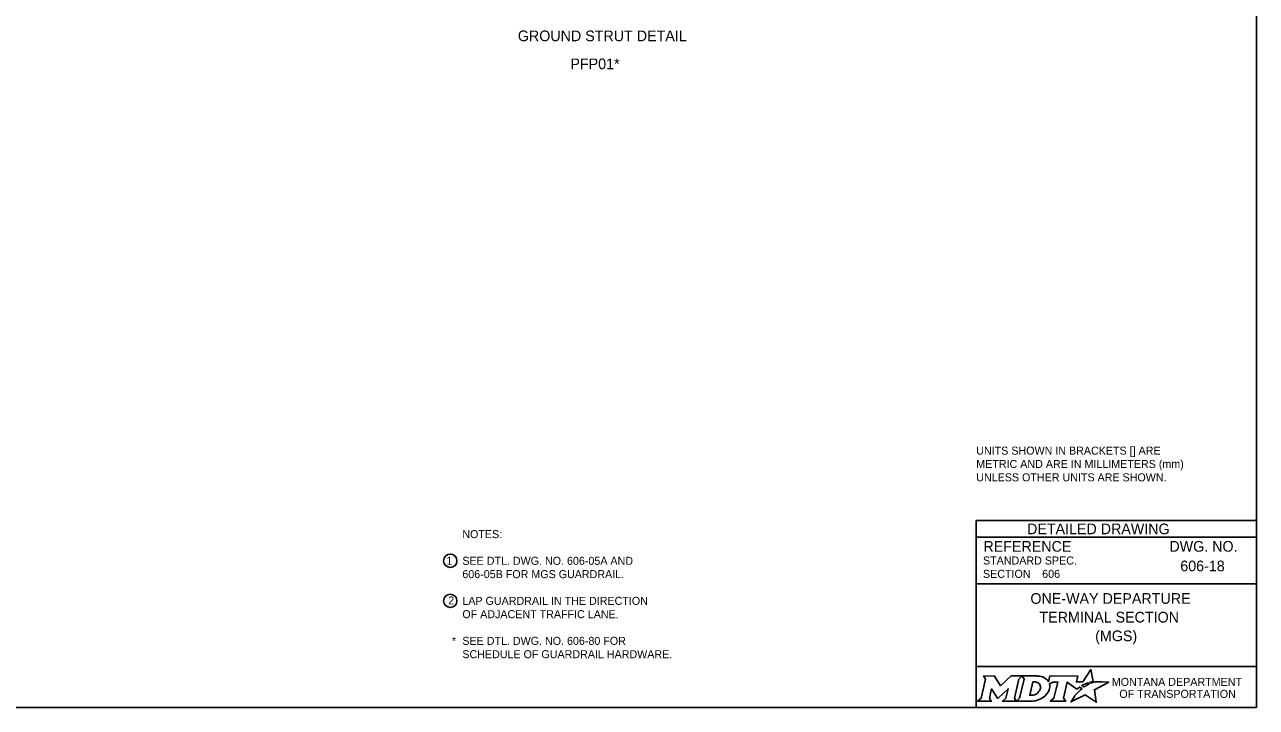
# Model space of a CAD drawing. Extents: x 49991.4 to 50021, y 49987.6 to 50011.4.
# Drawn here: x 50007.52 to 50016.75, y 49987.8 to 49992.92 of the extents above; entities that cross this region are included whole.
import ezdxf

# ---------------------------------------------------------------- set-up
doc = ezdxf.new("R2010")
doc.units = 0
for name, color, linetype in [('Default', 7, 'Continuous'), ('Level 1', 7, 'Continuous'), ('Level 2', 7, 'Continuous'), ('Level 5', 7, 'Continuous')]:
    doc.layers.add(name, color=color, linetype=linetype)

msp = doc.modelspace()

# ---------------------------------------------------------------- linework, layer by layer
at = {"layer": 'Default'}
for points in [[(50014.7056, 49988.0338), (50014.7197, 49988.0104), (50014.6862, 49987.8671), (50014.6605, 49987.8446), (50014.7621, 49987.8446), (50014.7486, 49987.8674), (50014.7648, 49987.9375), (50014.8085, 49987.8685), (50014.8138, 49987.8685), (50014.8889, 49987.938), (50014.8725, 49987.8669), (50014.8478, 49987.8449), (50014.9494, 49987.8449), (50014.9356, 49987.8682), (50014.9688, 49988.0106)], [(50014.9688, 49988.0106), (50014.9941, 49988.0338), (50014.9117, 49988.0338), (50014.8321, 49987.9608), (50014.7876, 49988.0335), (50014.7056, 49988.0338)], [(50015.1077, 49988.0338), (50014.9941, 49988.0338), (50015.0088, 49988.0109), (50014.9749, 49987.8671), (50014.9494, 49987.8449), (50015.06, 49987.8449)], [(50015.5126, 49987.9811), (50015.5023, 49987.9867), (50015.5139, 49987.9895), (50015.5255, 49987.9915), (50015.5081, 49988.0816), (50015.4486, 49987.9903), (50015.4013, 49987.9896), (50015.4116, 49988.0337), (50015.2024, 49988.0338), (50015.1923, 49987.9913), (50015.1865, 49987.9996)], [(50015.1317, 49987.9471), (50015.1305, 49987.939), (50015.1273, 49987.9297), (50015.1231, 49987.9215), (50015.1175, 49987.914), (50015.111, 49987.9071), (50015.1031, 49987.9008), (50015.0948, 49987.8961), (50015.0857, 49987.8922), (50015.0766, 49987.8899), (50015.0674, 49987.889), (50015.0515, 49987.889), (50015.0751, 49987.989), (50015.0911, 49987.989), (50015.0987, 49987.9884), (50015.1063, 49987.9865), (50015.1129, 49987.9835), (50015.119, 49987.9793), (50015.1238, 49987.9743), (50015.1275, 49987.9683), (50015.1302, 49987.9621), (50015.1318, 49987.9547), (50015.1318, 49987.9517), (50015.1317, 49987.9471)], [(50015.1991, 49987.9747), (50015.2237, 49987.9878), (50015.2606, 49987.9878), (50015.232, 49987.8673), (50015.2045, 49987.8446), (50015.3207, 49987.8446), (50015.3037, 49987.8675), (50015.3319, 49987.9877), (50015.4032, 49987.936), (50015.4243, 49987.9511), (50015.444, 49987.9402)], [(50015.3882, 49987.8843), (50015.3729, 49987.8599), (50015.3682, 49987.8524), (50015.3624, 49987.8438), (50015.3601, 49987.8395), (50015.4654, 49987.8926), (50015.5493, 49987.8375), (50015.5362, 49987.9302), (50015.6431, 49987.9886), (50015.5938, 49987.9894), (50015.5637, 49987.9898), (50015.5429, 49987.9901), (50015.5361, 49987.9886), (50015.5312, 49987.9874), (50015.5228, 49987.9851), (50015.5126, 49987.9811)], [(50015.4622, 49987.9535), (50015.4598, 49987.9518), (50015.4415, 49987.9614), (50015.4518, 49987.9671), (50015.4559, 49987.9693), (50015.4645, 49987.9733), (50015.4702, 49987.9759), (50015.4781, 49987.9789), (50015.4854, 49987.9816), (50015.4972, 49987.9742), (50015.4932, 49987.9721), (50015.4886, 49987.9696), (50015.4844, 49987.9674), (50015.4794, 49987.9645), (50015.4775, 49987.9634), (50015.4748, 49987.9618), (50015.4723, 49987.9604), (50015.47, 49987.9588), (50015.4674, 49987.957), (50015.4647, 49987.9552), (50015.4622, 49987.9535)], [(50015.1057, 49987.8522), (50015.1141, 49987.8548), (50015.1271, 49987.8602), (50015.1475, 49987.8712)], [(50015.4021, 49987.9004), (50015.4021, 49987.9004)]]:
    msp.add_lwpolyline(points, dxfattribs=at)
for centre, radius, start, end in [((50015.1308, 49987.9554), 0.0709, 339.53292, 15.85821), ((50015.0868, 49987.9727), 0.1183, 300.91025, 339.13831)]:
    msp.add_arc(centre, radius, start, end, dxfattribs=at)
for centre, major_axis, ratio, start_param, end_param in [((50015.1056, 49987.9864), (0.0834, -0.0037), 0.568097, 0.61298, 1.570796), ((50015.1612, 49987.9937), (0.0361, -0.0295), 0.469099, 1.225588, 1.570796), ((50015.4329, 49987.9305), (-0.0112, -0.0097), 0.021651, 3.157348, 6.283185), ((50015.0603, 49987.9932), (0, 0.1484), 0.987302, 3.139398, 3.456847), ((50015.3952, 49987.8923), (-0.00694, -0.00806), 0.008222, 0, 3.137361), ((50015.4119, 49987.9106), (-0.0098, -0.0102), 0.016458, 3.141593, 6.279097)]:
    msp.add_ellipse(centre, major_axis=major_axis, ratio=ratio, start_param=start_param, end_param=end_param, dxfattribs=at)
at = {"layer": 'Level 1'}
msp.add_lwpolyline([(49999.3835, 49998.9992), (50016.7501, 49998.9992), (50016.7501, 49987.7988), (49999.3835, 49987.7988)], close=True, dxfattribs=at)
at = {"layer": 'Level 2'}
for centre in [(50010.7071, 49988.8971), (50010.7071, 49988.5971)]:
    msp.add_circle(centre, 0.05, dxfattribs=at)
at = {"layer": 'Level 5'}
for p, q in [((50016.7501, 49989.1988), (50014.6501, 49989.1988)), ((50014.6501, 49989.1988), (50014.6501, 49987.7988)), ((50016.7501, 49989.0738), (50014.6501, 49989.0738)), ((50016.3862, 49988.8587), (50016.3862, 49988.8587)), ((50015.1444, 49988.7993), (50015.1444, 49988.7993)), ((50016.7501, 49988.7238), (50014.6501, 49988.7238)), ((50015.7001, 49988.4747), (50015.7001, 49988.4747)), ((50016.7501, 49988.1057), (50014.6501, 49988.1057))]:
    msp.add_line(p, q, dxfattribs=at)

# ---------------------------------------------------------------- texts
at = {"layer": 'Default'}
for s, p in [('MONTANA DEPARTMENT', (50015.6663, 49987.96)), ('OF TRANSPORTATION', (50015.7225, 49987.87))]:
    msp.add_text(s, height=0.06, dxfattribs=at).set_placement(p)
at = {"layer": 'Level 2'}
for s, height, p in [('GROUND STRUT DETAIL', 0.08, (50011.2132, 49992.7913)), ('PFP01*', 0.08, (50011.6075, 49992.5815)), ('UNITS SHOWN IN BRACKETS [] ARE ', 0.06, (50014.6501, 49989.6928)), ('METRIC AND ARE IN MILLIMETERS (mm) ', 0.06, (50014.6501, 49989.5928)), ('UNLESS OTHER UNITS ARE SHOWN.', 0.06, (50014.6501, 49989.4928)), ('NOTES:', 0.06, (50010.7972, 49989.0671)), ('1', 0.06, (50010.6775, 49988.8676)), ('SEE DTL. DWG. NO. 606-05A AND', 0.06, (50010.7972, 49988.8671)), ('606-18', 0.08, (50016.1798, 49988.8187)), ('606-05B FOR MGS GUARDRAIL.', 0.06, (50010.7972, 49988.7671)), ('606', 0.06, (50015.1444, 49988.7693)), ('2', 0.06, (50010.6913, 49988.5703)), ('LAP GUARDRAIL IN THE DIRECTION', 0.06, (50010.7972, 49988.5671)), ('ONE-WAY DEPARTURE', 0.08, (50015.0562, 49988.5747)), ('OF ADJACENT TRAFFIC LANE.', 0.06, (50010.7972, 49988.4671)), ('TERMINAL SECTION', 0.08, (50015.1239, 49988.4347)), ('*', 0.06, (50010.7189, 49988.2671)), ('SEE DTL. DWG. NO. 606-80 FOR', 0.06, (50010.7972, 49988.2671)), ('(MGS)', 0.08, (50015.5417, 49988.2947)), ('SCHEDULE OF GUARDRAIL HARDWARE.', 0.06, (50010.7972, 49988.1671))]:
    msp.add_text(s, height=height, dxfattribs=at).set_placement(p)
at = {"layer": 'Level 5'}
for s, height, p in [('DETAILED DRAWING', 0.0799, (50015.0311, 49989.0963)), ('REFERENCE', 0.08, (50014.7037, 49988.9654)), ('DWG. NO.', 0.08, (50016.0979, 49988.9654)), ('STANDARD SPEC.', 0.06, (50014.7004, 49988.8694)), ('SECTION', 0.06, (50014.7004, 49988.7694))]:
    msp.add_text(s, height=height, dxfattribs=at).set_placement(p)

doc.saveas('drawing.dxf')
